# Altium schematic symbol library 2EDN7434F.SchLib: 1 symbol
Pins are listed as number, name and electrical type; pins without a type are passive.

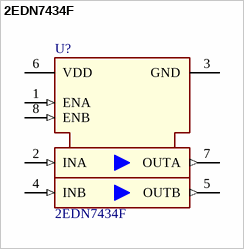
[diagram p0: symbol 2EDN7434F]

## 2EDN7434F
designator U?
2 channel Low side gate driver with non inverting input, 4.2V UVLO; Manufacturer: Infineon Technologies
pins: 1 ENA (in) "Enable Input channel A", 2 INA (in) "Input Signal channel A", 3 GND (power) "Ground", 4 INB (in) "Input Signal channel B", 5 OUTB (out) "Driver Output Channel B", 6 VDD (power) "Positive Supply Voltage", 7 OUTA (out) "Driver Output Channel A", 8 ENB (in) "Enable Input channel B"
